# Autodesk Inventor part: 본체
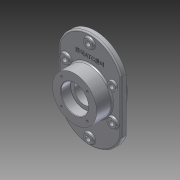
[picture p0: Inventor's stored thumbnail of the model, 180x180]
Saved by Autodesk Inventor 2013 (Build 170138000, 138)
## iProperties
Created: 2015-02
Part Number: 본체
Material: 알루미늄 6061
Document SubType Name: Modeling
Designer: kb
Density: 2.71 g/cm^3
Mass: 1636.71 g
Surface Area: 926.529 cm^2
Volume: 603.951 cm^3
Author: kb
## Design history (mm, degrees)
sketch "스케치1"
  geometry: L1 (-70, -60)-(70, -60); L2 (70, -60)-(70, 60); L3 (70, 60)-(-70, 60); L4 (-70, 60)-(-70, -60); L5 (-70, -60)-(70, 60); L6 (70, -60)-(-70, 60); A1 r 74 centre (0, 36) between (70, 60) and (-70, 60); A2 r 74 centre (0, -36) between (-70, -60) and (70, -60); 3 further points
  constraints: 12 end point, 6 point on circle, 2 centre point, 2 midpoint, 2 parallel, 1 horizontal, 1 perpendicular
  dimensions: "d0" = 120 distance of L1.end L2.end; "d2" = 140 distance of L2.end L3.end; "d3" = 50 distance from line of L3 point (0, 110); "d4" = 50 distance from line of point (0, -110) L1
extrude "돌출1" new body sketch "스케치1" distance "d5" = 12; taper "d6" = 0 deg
sketch "스케치2"
  geometry: L1 (60, 0)-(60, 0) reference; L2 (60, 0)-(60, 12) reference; L3 (60, 12)-(60, 12) reference; L4 (60, 0)-(60, 12) reference; L5 (-60, 0)-(-60, 0) reference; L6 (-60, 0)-(-60, 12) reference; L7 (-60, 12)-(-60, 12) reference; L8 (-60, 0)-(-60, 12) reference; L9 (-60, 12)-(60, 12) reference; L10 (-60, 0)-(60, 0) reference; L11 (110, 0)-(110, 12) reference; L12 (110, 12)-(60, 12) reference; L13 (-60, 12)-(-110, 12) reference; L14 (-110, 0)-(-110, 12) reference; L15 (0, 55.915)-(0, -38.906); L16 (50, 47)-(50, -23); L17 (31, 47)-(31, 25); L18 (0, 25)-(0, -1); L19 (31, -1)-(31, -23); L20 (31, 25)-(22.5, 25); L21 (22.5, 25)-(22.5, -1); L22 (22.5, -1)-(31, -1); L23 (50, 47)-(31, 47); L24 (50, -23)-(31, -23); L25 (-60, 0)-(60, 0) reference; L26 (60, 0)-(60, 12) reference; L27 (-60, 12)-(60, 12) reference; L28 (-60, 0)-(-60, 12) reference; 2 further points
  constraints: 20 end point, 3 parallel, 2 perpendicular, 1 midpoint, 1 point on line
  dimensions: "d7" = 70 distance of L16.start L16.end; "d10" = 100 diameter of L16 L15; "d11" = 22 distance of L17.start L17.end; "d12" = 22 distance of L19.start L19.end; "d13" = 62 diameter of L19 L15; "d14" = 62 diameter of L17 L15; "d62" = 45 diameter of L21 L15; "d63" = 23 distance between parallel lines of L24 L10
revolve "회전1" sketch "스케치2" stored, may be unused: angle "d16" = 90 deg
sketch "스케치3"
  geometry: L1 (70, -60)-(70, 60) reference; L2 (-70, 60)-(-70, -60) reference; L3 (53, 56.976)-(53, -56.976); L4 (-53, -56.976)-(-53, 56.976); L5 (-84.709, 0)-(99.231, 0); C1 r 10 at (0, 93); C2 r 10 at (0, -93); C3 r 10 at (-53, 36); C4 r 10 at (-53, -36); C5 r 10 at (53, 36); C6 r 10 at (53, -36); C7 r 50 at (0, 0) reference; A1 r 74 centre (0, -36) between (-70, -60) and (70, -60) reference; A2 r 74 centre (0, 36) between (70, 60) and (-70, 60) reference; A3 r 57 centre (0, 36) between (53, 56.976) and (-53, 56.976); A4 r 57 centre (0, -36) between (-53, -56.976) and (53, -56.976)
  constraints: 8 centre point, 6 end point, 6 point on circle, 5 equal radius, 5 point on line, 1 perpendicular, 5 other
  dimensions: "d17" = 17 distance between parallel lines of L2 L4; "d18" = 20 diameter of C1; "d89" = 72 distance of C4.centre C3.centre; "d90" = 72 distance of C6.centre C5.centre
extrude "돌출2" join sketch "스케치3" distance "d19" = 5; taper "d20" = 0 deg
sketch "스케치7"
  geometry: C1 r 10 at (0, 0) reference; C2 r 10 at (-53, -57) reference; C3 r 10 at (-53, -129) reference; C4 r 10 at (0, -186) reference; C5 r 10 at (53, -129) reference; C6 r 10 at (53, -57) reference; 1 further point
hole "구멍3" sketch "스케치7" at (0, 0), (53, -57), (53, -129), (0, -186), (-53, -129), (-53, -57) diameter "d47" = 11; stored, may be unused: countersink angle "d51" = 90 deg, drill point angle "d53" = 118 deg; dims "d48" = 10, "d49" = 4, "d50" = 2, "d52" = 13
fillet "모깎기1" dims "d54" = 0.3
fillet "모깎기2" dims "d55" = 3
chamfer "모따기1" distance "d56" = 1; stored, may be unused: second distance "d57" = 2, angle "d58" = 45 deg
sketch "스케치8"
  geometry: L1 (0, 154)-(0, -154) reference; L2 (-99.159, 0)-(99.159, 0) reference; 1 further point
  constraints: 1 point on line, 1 other
  dimensions: "d59" = 65 distance from line of L2 point (0, 65)
feature "엠보싱1" sketch "스케치8" dims "d0" = 120, "d2" = 140, "d3" = 50, "d4" = 50, "d60" = 1, "d61" = 0
sketch "스케치9"
  geometry: C1 r 22.5 at (0, 0) reference; C2 r 22.5 at (0, 0) reference; C3 r 22.5 at (0, 0)
  constraints: 1 centre point, 1 coincident
extrude "돌출3" cut sketch "스케치9" stored distance "d64" = 5; taper "d65" = 0 deg
sketch "스케치10" dims "d66" = 82
  geometry: L1 (0, 0)-(-28.991, 28.991); L2 (-84.24, 0)-(108.171, 0); L3 (0, 116.817)-(0, -134.614); C1 r 50 at (0, 0) reference; C2 r 50 at (0, 0) reference; C3 r 32 at (0, 0) reference; 3 further points
  constraints: 6 end point, 3 symmetric about line, 2 point on line, 1 coincident, 1 horizontal, 1 perpendicular, 3 other
  dimensions: "d69" = 45 deg angle of L2 L1
hole "구멍4" sketch "스케치10" at (-28.991, 28.991), (28.991, 28.991), (-28.991, -28.991), (28.991, -28.991) diameter "d71" = 4.917; stored, may be unused: countersink angle "d75" = 90 deg, drill point angle "d77" = 118 deg; dims "d72" = 10, "d73" = 4, "d74" = 2, "d76" = 13
sketch "스케치11" dims "d78" = 82
  geometry: L1 (-101.243, 0)-(126.277, 0); L2 (0, 135.665)-(0, -138.61); L3 (0, 0)-(-28.991, 28.991); C1 r 50 at (0, 0) reference; C2 r 50 at (0, 0) reference; C3 r 32 at (0, 0) reference; 3 further points
  constraints: 6 end point, 3 symmetric about line, 2 point on line, 1 coincident, 1 horizontal, 1 perpendicular, 3 other
  dimensions: "d80" = 45 deg angle of L1 L3
hole "구멍5" sketch "스케치11" at (-28.991, 28.991), (-28.991, -28.991), (28.991, -28.991), (28.991, 28.991) diameter "d82" = 4.917; stored, may be unused: countersink angle "d86" = 90 deg, drill point angle "d88" = 118 deg; dims "d83" = 10, "d84" = 4, "d85" = 2, "d87" = 13
node "솔리드1"
node "투영된 루프1"
node "투영된 루프2"
node "투영된 루프3"
node "투영된 루프4"
node "투영된 루프5"
node "투영된 루프6"
node "투영된 루프7"
node "투영된 루프8"
node "투영된 루프9"
node "투영된 루프10"
node "투영된 루프11"
